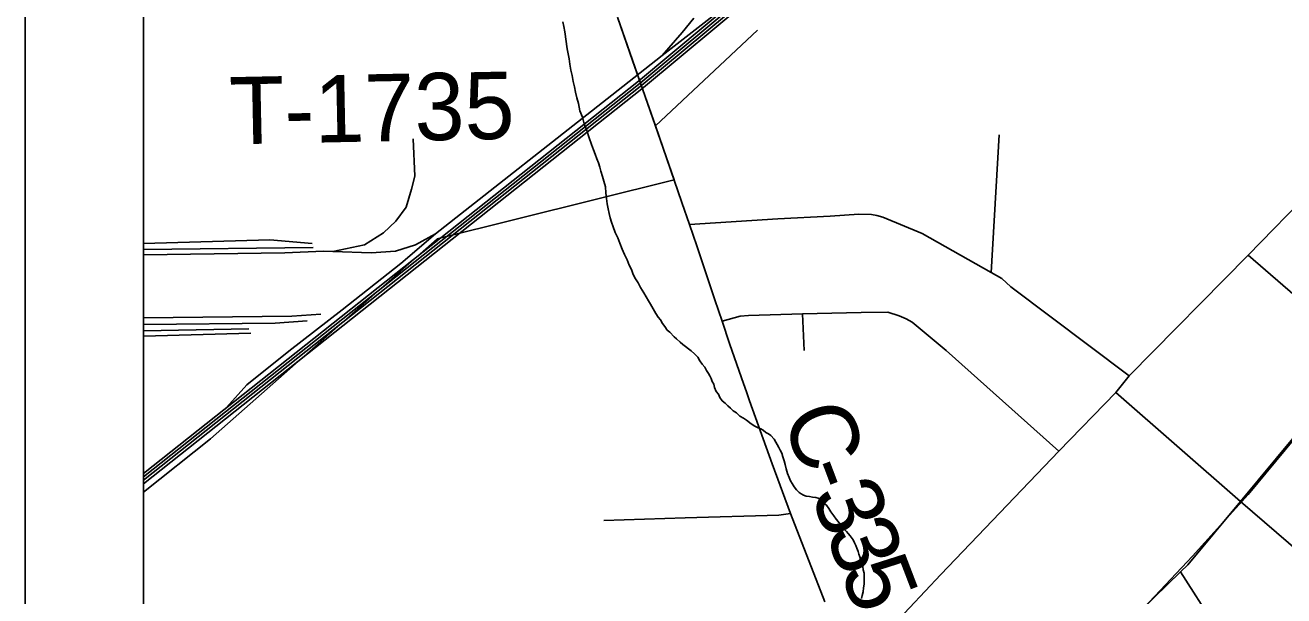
# Model space of a CAD drawing. Extents: x -59 to 82, y -3 to 49.
# Drawn here: x -54.998 to -53.935, y 45.421 to 45.903 of the extents above; entities that cross this region are included whole.
import ezdxf

# ---------------------------------------------------------------- set-up
doc = ezdxf.new("R2010")
doc.units = 0
for name, color, linetype in [('GM_X_City_Street', 7, 'Continuous'), ('GM_X_Corporation', 7, 'Continuous'), ('GM_X_County_Road', 7, 'Continuous'), ('GM_X_County_Road_Text', 7, 'Continuous'), ('GM_X_Minor_River', 7, 'Continuous'), ('GM_X_Rail_Line', 7, 'Continuous'), ('GM_X_Township_Road', 7, 'Continuous'), ('GM_X_Township_Road_Text', 7, 'Continuous'), ('GM_X_US_Route', 7, 'Continuous'), ('SH_Data', 7, 'Continuous')]:
    doc.layers.add(name, color=color, linetype=linetype)

msp = doc.modelspace()

# ---------------------------------------------------------------- linework, layer by layer
at = {"layer": 'GM_X_City_Street'}
for p, q in [((-54.4655, 45.8182), (-54.3794, 45.8991)), ((-54.1819, 45.6943), (-54.1753, 45.8108)), ((-54.3621, 45.7396), (-54.4369, 45.735)), ((-54.318, 45.7421), (-54.3621, 45.7396)), ((-54.2938, 45.7437), (-54.318, 45.7421)), ((-54.283, 45.7435), (-54.2938, 45.7437)), ((-54.2787, 45.7426), (-54.283, 45.7435)), ((-54.2736, 45.7412), (-54.2787, 45.7426)), ((-54.2404, 45.7272), (-54.2736, 45.7412)), ((-54.1819, 45.6943), (-54.2404, 45.7272)), ((-53.9076, 45.6594), (-53.965, 45.7089)), ((-54.1731, 45.6892), (-54.1819, 45.6943)), ((-54.1654, 45.6824), (-54.1731, 45.6892)), ((-54.0655, 45.6071), (-54.1654, 45.6824)), ((-54.4092, 45.6532), (-54.3939, 45.6574)), ((-54.3939, 45.6574), (-54.387, 45.6581)), ((-54.387, 45.6581), (-54.3415, 45.6594)), ((-54.3415, 45.6594), (-54.2918, 45.6605)), ((-54.3415, 45.6594), (-54.34, 45.6284)), ((-54.2918, 45.6605), (-54.2694, 45.6609)), ((-54.2694, 45.6609), (-54.2597, 45.6579)), ((-54.2597, 45.6579), (-54.2537, 45.6552)), ((-54.2537, 45.6552), (-54.2486, 45.6525)), ((-54.2486, 45.6525), (-54.2201, 45.6284)), ((-54.2201, 45.6284), (-54.1723, 45.5859)), ((-54.1723, 45.5859), (-54.1248, 45.5435)), ((-53.9762, 45.3701), (-54.0222, 45.4414))]:
    msp.add_line(p, q, dxfattribs=at)
at = {"layer": 'GM_X_Corporation'}
for p, q in [((-54.898, 48.5155), (-54.898, 42.4912)), ((-54.898, 48.5155), (-54.898, 43.4634)), ((-54.4977, 45.91), (-54.4657, 45.8188)), ((-54.4657, 45.8188), (-54.4498, 45.7727)), ((-54.4498, 45.7727), (-54.65, 45.7229)), ((-54.65, 45.7229), (-54.8415, 45.5539)), ((-54.8415, 45.5539), (-54.898, 45.5089)), ((-54.898, 45.5089), (-54.898, 45.416))]:
    msp.add_line(p, q, dxfattribs=at)
at = {"layer": 'GM_X_County_Road'}
for p, q in [((-54.485, 45.8735), (-54.4975, 45.9094)), ((-54.4655, 45.8182), (-54.485, 45.8735)), ((-54.4432, 45.7535), (-54.4655, 45.8182)), ((-53.965, 45.7089), (-53.8577, 45.8195)), ((-54.4369, 45.735), (-54.4432, 45.7535)), ((-54.4307, 45.7168), (-54.4369, 45.735)), ((-54.4184, 45.6805), (-54.4307, 45.7168)), ((-54.0655, 45.6071), (-53.965, 45.7089)), ((-54.4154, 45.6714), (-54.4184, 45.6805)), ((-54.4092, 45.6532), (-54.4154, 45.6714)), ((-54.4029, 45.6343), (-54.4092, 45.6532)), ((-54.3928, 45.6053), (-54.4029, 45.6343)), ((-54.3885, 45.5927), (-54.3928, 45.6053)), ((-54.0766, 45.593), (-54.0655, 45.6071)), ((-54.3861, 45.586), (-54.3885, 45.5927)), ((-54.1248, 45.5435), (-54.0766, 45.593)), ((-54.0766, 45.593), (-53.9714, 45.501)), ((-54.3671, 45.5328), (-54.3861, 45.586)), ((-54.2246, 45.4391), (-54.1248, 45.5435)), ((-54.3514, 45.4909), (-54.3671, 45.5328)), ((-53.9714, 45.501), (-53.9078, 45.446)), ((-54.3226, 45.4162), (-54.3514, 45.4909)), ((-54.3003, 45.3588), (-54.2246, 45.4391))]:
    msp.add_line(p, q, dxfattribs=at)
at = {"layer": 'GM_X_Minor_River'}
for p, q in [((-54.5439, 45.9063), (-54.543, 45.9021)), ((-54.543, 45.9021), (-54.5421, 45.8976)), ((-54.5421, 45.8976), (-54.5402, 45.8835)), ((-54.5402, 45.8835), (-54.5394, 45.879)), ((-54.5394, 45.879), (-54.5385, 45.8748)), ((-54.5385, 45.8748), (-54.538, 45.8703)), ((-54.538, 45.8703), (-54.5371, 45.8653)), ((-54.5371, 45.8653), (-54.5358, 45.8608)), ((-54.5358, 45.8608), (-54.535, 45.8559)), ((-54.535, 45.8559), (-54.5341, 45.8513)), ((-54.5341, 45.8513), (-54.5332, 45.8468)), ((-54.5332, 45.8468), (-54.5319, 45.8419)), ((-54.5319, 45.8419), (-54.5307, 45.8373)), ((-54.5307, 45.8373), (-54.5294, 45.8309)), ((-54.5294, 45.8309), (-54.5273, 45.8256)), ((-54.5273, 45.8256), (-54.5257, 45.8199)), ((-54.5257, 45.8199), (-54.5236, 45.8143)), ((-54.5236, 45.8143), (-54.5215, 45.8082)), ((-54.5215, 45.8082), (-54.5195, 45.8026)), ((-54.5195, 45.8026), (-54.5179, 45.7981)), ((-54.5179, 45.7981), (-54.5166, 45.7943)), ((-54.5166, 45.7943), (-54.515, 45.7905)), ((-54.515, 45.7905), (-54.5138, 45.7871)), ((-54.5138, 45.7871), (-54.5125, 45.7834)), ((-54.5125, 45.7834), (-54.5117, 45.7799)), ((-54.5117, 45.7799), (-54.5104, 45.7754)), ((-54.5104, 45.7754), (-54.5092, 45.7716)), ((-54.5092, 45.7716), (-54.5079, 45.7667)), ((-54.5079, 45.7667), (-54.5074, 45.7618)), ((-54.5074, 45.7618), (-54.5069, 45.7568)), ((-54.5069, 45.7568), (-54.5064, 45.7523)), ((-54.5064, 45.7523), (-54.5055, 45.7481)), ((-54.5055, 45.7481), (-54.5047, 45.7443)), ((-54.5047, 45.7443), (-54.5038, 45.7405)), ((-54.5038, 45.7405), (-54.5026, 45.7368)), ((-54.5026, 45.7368), (-54.5013, 45.733)), ((-54.5013, 45.733), (-54.4997, 45.7281)), ((-54.4997, 45.7281), (-54.4973, 45.7236)), ((-54.4973, 45.7236), (-54.4956, 45.7191)), ((-54.4956, 45.7191), (-54.4936, 45.7142)), ((-54.4936, 45.7142), (-54.4916, 45.7096)), ((-54.4916, 45.7096), (-54.4896, 45.7051)), ((-54.4896, 45.7051), (-54.4879, 45.7006)), ((-54.4879, 45.7006), (-54.4859, 45.6968)), ((-54.4859, 45.6968), (-54.4843, 45.6927)), ((-54.4843, 45.6927), (-54.4823, 45.6889)), ((-54.4823, 45.6889), (-54.4803, 45.6856)), ((-54.4803, 45.6856), (-54.4783, 45.6818)), ((-54.4783, 45.6818), (-54.4755, 45.6773)), ((-54.4755, 45.6773), (-54.4735, 45.6739)), ((-54.4735, 45.6739), (-54.4715, 45.6705)), ((-54.4715, 45.6705), (-54.4699, 45.6675)), ((-54.4699, 45.6675), (-54.4652, 45.6597)), ((-54.4652, 45.6597), (-54.4632, 45.6567)), ((-54.4632, 45.6567), (-54.4612, 45.6544)), ((-54.4612, 45.6544), (-54.4596, 45.6514)), ((-54.4596, 45.6514), (-54.4576, 45.6488)), ((-54.4576, 45.6488), (-54.4557, 45.6458)), ((-54.4557, 45.6458), (-54.4533, 45.644)), ((-54.4533, 45.644), (-54.4498, 45.6399)), ((-54.4498, 45.6399), (-54.4479, 45.6384)), ((-54.4479, 45.6384), (-54.4447, 45.6354)), ((-54.4447, 45.6354), (-54.4424, 45.6336)), ((-54.4424, 45.6336), (-54.4401, 45.6318)), ((-54.4401, 45.6318), (-54.4377, 45.6299)), ((-54.4377, 45.6299), (-54.4354, 45.6281)), ((-54.4354, 45.6281), (-54.4327, 45.6258)), ((-54.4327, 45.6258), (-54.4299, 45.6229)), ((-54.4299, 45.6229), (-54.428, 45.6199)), ((-54.428, 45.6199), (-54.426, 45.6169)), ((-54.426, 45.6169), (-54.424, 45.6143)), ((-54.424, 45.6143), (-54.4224, 45.6116)), ((-54.4224, 45.6116), (-54.4208, 45.609)), ((-54.4208, 45.609), (-54.4196, 45.6071)), ((-54.4196, 45.6071), (-54.4184, 45.6049)), ((-54.4184, 45.6049), (-54.4176, 45.6022)), ((-54.4176, 45.6022), (-54.4164, 45.6)), ((-54.4164, 45.6), (-54.4156, 45.5973)), ((-54.4156, 45.5973), (-54.4143, 45.5939)), ((-54.4143, 45.5939), (-54.4124, 45.5917)), ((-54.4124, 45.5917), (-54.4112, 45.5887)), ((-54.4112, 45.5887), (-54.4092, 45.5861)), ((-54.4092, 45.5861), (-54.4068, 45.5839)), ((-54.4068, 45.5839), (-54.4045, 45.5816)), ((-54.4045, 45.5816), (-54.4022, 45.5798)), ((-54.4022, 45.5798), (-54.3998, 45.5776)), ((-54.3998, 45.5776), (-54.3971, 45.5757)), ((-54.3971, 45.5757), (-54.3944, 45.5731)), ((-54.3944, 45.5731), (-54.3913, 45.5713)), ((-54.3913, 45.5713), (-54.3886, 45.5695)), ((-54.3886, 45.5695), (-54.3847, 45.5665)), ((-54.3847, 45.5665), (-54.3816, 45.5647)), ((-54.3816, 45.5647), (-54.3789, 45.5632)), ((-54.3789, 45.5632), (-54.3766, 45.5622)), ((-54.3766, 45.5622), (-54.3746, 45.5611)), ((-54.3746, 45.5611), (-54.3723, 45.5592)), ((-54.3723, 45.5592), (-54.37, 45.5581)), ((-54.37, 45.5581), (-54.3681, 45.5567)), ((-54.3681, 45.5567), (-54.3653, 45.5537)), ((-54.3653, 45.5537), (-54.3613, 45.5466)), ((-54.3613, 45.5466), (-54.3601, 45.5443)), ((-54.3601, 45.5443), (-54.3589, 45.5417)), ((-54.3589, 45.5417), (-54.3581, 45.5386)), ((-54.3581, 45.5386), (-54.3568, 45.5353)), ((-54.3568, 45.5353), (-54.356, 45.5322)), ((-54.356, 45.5322), (-54.3551, 45.5284)), ((-54.3551, 45.5284), (-54.3539, 45.5247)), ((-54.3539, 45.5247), (-54.3527, 45.5213)), ((-54.3527, 45.5213), (-54.3514, 45.5183)), ((-54.3514, 45.5183), (-54.3502, 45.516)), ((-54.3502, 45.516), (-54.3483, 45.5134)), ((-54.3483, 45.5134), (-54.3463, 45.5108)), ((-54.3463, 45.5108), (-54.3443, 45.5085)), ((-54.3443, 45.5085), (-54.3424, 45.5074)), ((-54.3424, 45.5074), (-54.3405, 45.5064)), ((-54.3405, 45.5064), (-54.3382, 45.5053)), ((-54.3382, 45.5053), (-54.3355, 45.505)), ((-54.3355, 45.505), (-54.3328, 45.5046)), ((-54.3328, 45.5046), (-54.3301, 45.5043)), ((-54.3301, 45.5043), (-54.3282, 45.5036)), ((-54.3282, 45.5036), (-54.3259, 45.5022)), ((-54.3259, 45.5022), (-54.3239, 45.4999)), ((-54.3239, 45.4999), (-54.3212, 45.4977)), ((-54.3212, 45.4977), (-54.3192, 45.4951)), ((-54.3192, 45.4951), (-54.3173, 45.4921)), ((-54.3173, 45.4921), (-54.3149, 45.4887)), ((-54.3149, 45.4887), (-54.3129, 45.4861)), ((-54.3129, 45.4861), (-54.3113, 45.4839)), ((-54.3113, 45.4839), (-54.309, 45.4809)), ((-54.309, 45.4809), (-54.307, 45.4786)), ((-54.307, 45.4786), (-54.3043, 45.4757)), ((-54.3043, 45.4757), (-54.3027, 45.4738)), ((-54.3027, 45.4738), (-54.3011, 45.4719)), ((-54.3011, 45.4719), (-54.2987, 45.4686)), ((-54.2987, 45.4686), (-54.2975, 45.4659)), ((-54.2975, 45.4659), (-54.2963, 45.4637)), ((-54.2963, 45.4637), (-54.2955, 45.4614)), ((-54.2955, 45.4614), (-54.2943, 45.4588)), ((-54.2943, 45.4588), (-54.2939, 45.4565)), ((-54.2939, 45.4565), (-54.293, 45.4543)), ((-54.293, 45.4543), (-54.2922, 45.4512)), ((-54.2922, 45.4512), (-54.2914, 45.4486)), ((-54.2914, 45.4486), (-54.2905, 45.4459)), ((-54.2905, 45.4459), (-54.2901, 45.4433)), ((-54.2901, 45.4433), (-54.2893, 45.4403)), ((-54.2894, 45.4311), (-54.2897, 45.4281)), ((-54.2893, 45.4403), (-54.2894, 45.4311)), ((-54.2911, 45.4216), (-54.2914, 45.4189)), ((-54.29, 45.4246), (-54.2911, 45.4216)), ((-54.2897, 45.4281), (-54.29, 45.4246))]:
    msp.add_line(p, q, dxfattribs=at)
at = {"layer": 'GM_X_Rail_Line'}
for p, q in [((-54.3281, 45.9813), (-54.46, 45.8776)), ((-54.48, 45.8561), (-54.3511, 45.9637)), ((-54.4785, 45.8544), (-54.3496, 45.9619)), ((-54.4771, 45.8526), (-54.3481, 45.9601)), ((-54.4756, 45.8508), (-54.3467, 45.9583)), ((-54.443, 45.8972), (-54.4332, 45.9093)), ((-54.46, 45.8776), (-54.443, 45.8972)), ((-54.46, 45.8776), (-54.5025, 45.8442)), ((-54.898, 45.5247), (-54.48, 45.8561)), ((-54.898, 45.5218), (-54.4785, 45.8544)), ((-54.898, 45.5188), (-54.4771, 45.8526)), ((-54.898, 45.5158), (-54.4756, 45.8508)), ((-54.5025, 45.8442), (-54.6514, 45.7271)), ((-54.6689, 45.7759), (-54.6702, 45.8072)), ((-54.6716, 45.7648), (-54.6689, 45.7759)), ((-54.6761, 45.7497), (-54.6716, 45.7648)), ((-54.685, 45.7379), (-54.6761, 45.7497)), ((-54.6953, 45.7278), (-54.685, 45.7379)), ((-54.898, 45.7189), (-54.7912, 45.7219)), ((-54.7912, 45.7219), (-54.7557, 45.7189)), ((-54.7113, 45.7179), (-54.6953, 45.7278)), ((-54.6806, 45.7019), (-54.6514, 45.7271)), ((-54.6514, 45.7271), (-54.6682, 45.7177)), ((-54.898, 45.7138), (-54.7547, 45.7155)), ((-54.7787, 45.711), (-54.898, 45.7093)), ((-54.7461, 45.7123), (-54.7787, 45.711)), ((-54.738, 45.712), (-54.7461, 45.7123)), ((-54.738, 45.712), (-54.7113, 45.7179)), ((-54.7057, 45.711), (-54.738, 45.712)), ((-54.6852, 45.7125), (-54.7057, 45.711)), ((-54.6682, 45.7177), (-54.6852, 45.7125)), ((-54.7303, 45.6628), (-54.6806, 45.7019)), ((-53.8053, 45.7001), (-53.9649, 45.5067)), ((-54.7727, 45.6575), (-54.898, 45.6561)), ((-54.7752, 45.628), (-54.7303, 45.6628)), ((-54.7483, 45.6592), (-54.7727, 45.6575)), ((-54.898, 45.6504), (-54.7868, 45.6516)), ((-54.898, 45.6451), (-54.8092, 45.6469)), ((-54.7868, 45.6516), (-54.7597, 45.6536)), ((-54.898, 45.6407), (-54.8075, 45.6432)), ((-54.8108, 45.5994), (-54.7752, 45.628)), ((-54.828, 45.5802), (-54.8108, 45.5994)), ((-53.9649, 45.5067), (-54.012, 45.4547)), ((-54.012, 45.4547), (-54.0531, 45.4112))]:
    msp.add_line(p, q, dxfattribs=at)
at = {"layer": 'GM_X_Township_Road'}
for p, q in [((-54.4406, 45.487), (-54.5092, 45.485)), ((-54.3615, 45.4895), (-54.4406, 45.487)), ((-54.3514, 45.4909), (-54.3615, 45.4895))]:
    msp.add_line(p, q, dxfattribs=at)
at = {"layer": 'GM_X_US_Route'}
for p, q in [((-53.9714, 45.501), (-53.9044, 45.5816)), ((-54.0159, 45.4475), (-53.9714, 45.501)), ((-54.0222, 45.4414), (-54.0159, 45.4475)), ((-54.0666, 45.398), (-54.0222, 45.4414))]:
    msp.add_line(p, q, dxfattribs=at)
at = {"layer": 'SH_Data'}
for p, q in [((-54.998, 49.3912), (-54.998, 42.3912)), ((-54.898, 49.2912), (-54.898, 42.4912))]:
    msp.add_line(p, q, dxfattribs=at)

# ---------------------------------------------------------------- texts
at = {"layer": 'GM_X_County_Road_Text'}
for s, rotation, p in [('C', 290.1, (-54.3592, 45.5731)), ('-', 290.723, (-54.343, 45.529)), ('3', 290.9162, (-54.3348, 45.5071)), ('3', 290.9385, (-54.3224, 45.4747)), ('5', 290.9389, (-54.31, 45.4423))]:
    msp.add_text(s, height=0.0568, rotation=rotation, dxfattribs=at).set_placement(p)
at = {"layer": 'GM_X_Township_Road_Text'}
msp.add_text('T-1735', height=0.05682, rotation=1.1694, dxfattribs=at).set_placement((-54.8249, 45.8026))

doc.saveas('drawing.dxf')
